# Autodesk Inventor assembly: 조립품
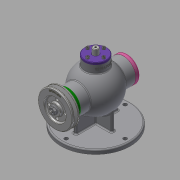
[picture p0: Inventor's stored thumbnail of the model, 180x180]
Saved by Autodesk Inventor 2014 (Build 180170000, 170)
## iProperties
Created: 2020-08
Part Number: 조립품
Document SubType Name: Assembly
Designer: kh
Author: kh
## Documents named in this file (18)
- C:\Users\kh\Desktop\700806V1032\조립품.iam
- C:\Users\kh\Desktop\700806V1032\본체.ipt
- C:\Users\kh\Desktop\700806V1032\V-벨트풀리.ipt
- C:\Users\kh\Desktop\700806V1032\너트 M8.ipt
- C:\Users\kh\Desktop\700806V1032\뒤커버.ipt
- C:\Users\kh\Desktop\700806V1032\멈춤링 15x1.ipt
- C:\Users\kh\Desktop\700806V1032\멈춤링 35x1.6.ipt
- 멈춤링 35x1.6.ipt
- C:\Users\kh\Desktop\700806V1032\베어링 6202.ipt
- 베어링 6202.ipt
- C:\Users\kh\Desktop\700806V1032\볼트 M4.ipt
- C:\Users\kh\Desktop\700806V1032\상부커버.ipt
- C:\Users\kh\Desktop\700806V1032\슬라이드.ipt
- C:\Users\kh\Desktop\700806V1032\앞커버.ipt
- C:\Users\kh\Desktop\700806V1032\오일 실 15 30 7.ipt
- C:\Users\kh\Desktop\700806V1032\칼라.ipt
- C:\Users\kh\Desktop\700806V1032\키 3x3x12.ipt
- C:\Users\kh\Desktop\700806V1032\편심축.ipt
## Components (1 placed, 1 different names)
1. V-벨트풀리:1 — Insert:10, Insert:11, Mate:6
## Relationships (3: Insert 2, Mate 1)
- Insert:10: V-벨트풀리:1
- Insert:11: V-벨트풀리:1
- Mate:6: V-벨트풀리:1
